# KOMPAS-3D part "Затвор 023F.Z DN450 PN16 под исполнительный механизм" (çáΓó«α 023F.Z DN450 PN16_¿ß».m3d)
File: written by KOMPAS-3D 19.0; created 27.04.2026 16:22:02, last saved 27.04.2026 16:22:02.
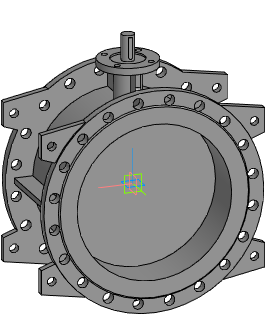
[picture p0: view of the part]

Document properties: Автор: Евгений; Полное имя файла: Z:\3.Личные\kachalov\3d для проектировщиков\1.7 Тип 023F.Z Затвор дисковый поворотный фланцевый с двумя эксцентриками\Затвор 023F.Z DN200-DN1600_исп\_stp_Затвор 023F.Z DN200-DN1600_исп\Затвор 023F.Z DN450 PN16_исп.m3d

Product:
- Part/product: Затвор 023F.Z DN450 PN16 под исполнительный механизм

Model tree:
1. Операция без истории:1  (labels: Затвор 023F.Z DN450 PN16 под исполнительный механизм)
